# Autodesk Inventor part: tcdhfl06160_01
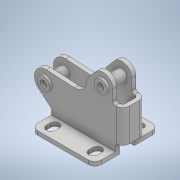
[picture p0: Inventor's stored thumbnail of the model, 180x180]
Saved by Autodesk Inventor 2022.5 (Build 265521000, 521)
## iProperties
Part Number: tcdhfl06160_01
Material: 一般
Document SubType Name: Modeling
Designer: ImaoCorp
Density: 1 g/cm^3
Appearance: 既定
Author: ImaoCorp
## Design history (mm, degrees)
feature "tcdhfl06160_01"
node "ソリッド1"
